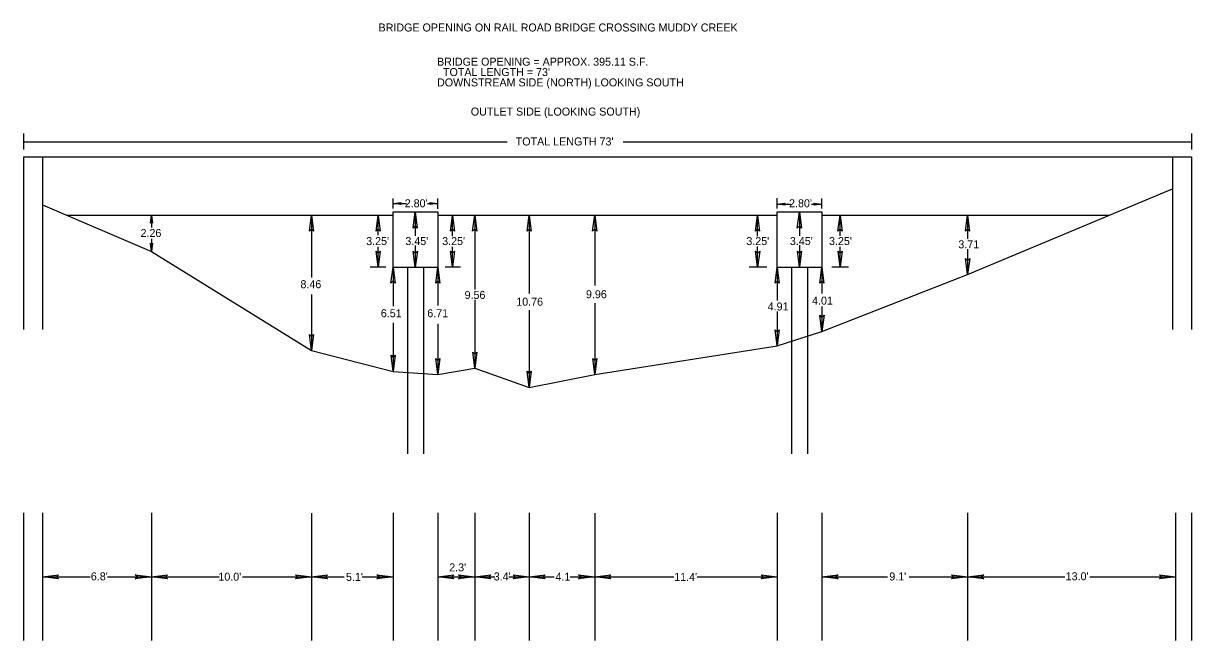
# Model space of a CAD drawing. Extents: x -200 to 949611, y -218 to 425120.
# Drawn here: x 948881 to 949611, y 424135 to 424521 of the extents above; entities that cross this region are included whole.
import ezdxf

# ---------------------------------------------------------------- set-up
doc = ezdxf.new("R2010")
doc.units = 0
doc.layers.add('SURVEY - PROFILE - Drainage - Bridge Hydraulic Data with Text', color=7, linetype='Continuous')

msp = doc.modelspace()

# ---------------------------------------------------------------- linework, layer by layer
at = {"layer": 'SURVEY - PROFILE - Drainage - Bridge Hydraulic Data with Text'}
for p, q in [((948880.64, 424451.86), (948880.64, 424441.85)), ((949610.64, 424451.86), (949610.64, 424441.85)), ((948880.64, 424446.65), (949182.88, 424446.65)), ((949255.53, 424446.65), (949610.64, 424446.65)), ((948880.64, 424437.28), (948892.64, 424437.28)), ((948880.64, 424437.28), (948880.64, 424329.47)), ((948892.64, 424437.28), (948892.64, 424329.47)), ((948892.64, 424437.28), (949598.64, 424437.28)), ((949598.64, 424437.28), (949598.64, 424329.47)), ((949598.64, 424437.28), (949610.64, 424437.28)), ((949610.64, 424437.28), (949610.64, 424329.47)), ((949470.64, 424363.78), (949598.64, 424417.28)), ((949111.64, 424405.01), (949111.64, 424411.31)), ((949111.64, 424408.14), (949120.13, 424408.14)), ((949133.21, 424408.14), (949139.64, 424408.14)), ((949139.64, 424404.94), (949139.64, 424411.31)), ((949351.64, 424405.04), (949351.64, 424411.41)), ((949351.64, 424407.7), (949359.96, 424407.7)), ((949373.01, 424407.7), (949379.64, 424407.7)), ((949379.64, 424405.01), (949379.64, 424411.38)), ((948892.64, 424407.28), (948960.64, 424378.28)), ((948907.64, 424400.88), (949111.64, 424400.88)), ((948960.64, 424400.88), (948960.64, 424393.08)), ((949060.64, 424400.88), (949060.64, 424361.9)), ((949102.32, 424388.33), (949102.32, 424400.88)), ((949111.64, 424402.88), (949139.64, 424402.88)), ((949111.64, 424368.38), (949111.64, 424402.88)), ((949125.56, 424402.88), (949125.56, 424388.01)), ((949139.64, 424402.88), (949139.64, 424368.38)), ((949139.64, 424400.88), (949351.64, 424400.88)), ((949148.81, 424387.85), (949148.81, 424400.88)), ((949162.64, 424400.88), (949162.64, 424354.38)), ((949196.64, 424400.88), (949196.64, 424352.04)), ((949237.64, 424400.88), (949237.64, 424356.86)), ((949339.47, 424387.86), (949339.47, 424400.88)), ((949351.64, 424402.88), (949379.64, 424402.88)), ((949351.64, 424368.38), (949351.64, 424402.88)), ((949365.52, 424402.88), (949365.52, 424387.99)), ((949379.64, 424402.88), (949379.64, 424368.38)), ((949379.64, 424400.88), (949559.4, 424400.88)), ((949390.93, 424387.93), (949390.93, 424400.88)), ((949470.64, 424400.88), (949470.64, 424386.1)), ((948960.64, 424386.07), (948960.64, 424378.28)), ((948960.64, 424378.28), (949060.64, 424316.28)), ((949102.32, 424368.38), (949102.32, 424381.19)), ((949125.56, 424381.99), (949125.56, 424368.38)), ((949148.81, 424368.38), (949148.81, 424381.19)), ((949339.47, 424368.38), (949339.47, 424381.28)), ((949365.52, 424382.05), (949365.52, 424368.38)), ((949390.93, 424368.38), (949390.93, 424381.08)), ((949470.64, 424379.59), (949470.64, 424363.78)), ((949107.12, 424368.38), (949097.44, 424368.38)), ((949111.64, 424368.38), (949139.64, 424368.38)), ((949111.64, 424368.38), (949111.64, 424344.08)), ((949120.64, 424368.38), (949120.64, 424251.68)), ((949130.64, 424368.38), (949130.64, 424251.68)), ((949139.64, 424368.38), (949139.64, 424344.36)), ((949153.68, 424368.38), (949144.13, 424368.38)), ((949345.12, 424368.38), (949334.1, 424368.38)), ((949351.64, 424368.38), (949379.64, 424368.38)), ((949351.64, 424368.38), (949351.64, 424347.48)), ((949360.64, 424368.38), (949360.64, 424251.68)), ((949370.64, 424368.38), (949370.64, 424251.68)), ((949379.64, 424368.38), (949379.64, 424351.9)), ((949379.64, 424328.28), (949470.64, 424363.78)), ((949396.21, 424368.38), (949385.8, 424368.38)), ((949060.64, 424351.3), (949060.64, 424316.28)), ((949162.64, 424347.98), (949162.64, 424305.28)), ((949237.64, 424345.96), (949237.64, 424301.28)), ((949379.64, 424343.87), (949379.64, 424328.28)), ((949196.64, 424341.58), (949196.64, 424293.28)), ((949351.64, 424340.71), (949351.64, 424319.28)), ((949111.64, 424333.63), (949111.64, 424303.28)), ((949139.64, 424333.01), (949139.64, 424301.28)), ((949351.64, 424319.28), (949379.64, 424328.28)), ((949060.64, 424316.28), (949111.64, 424303.28)), ((949237.64, 424301.28), (949351.64, 424319.28)), ((949139.64, 424301.28), (949162.64, 424305.28)), ((949162.64, 424305.28), (949196.64, 424293.28)), ((949111.64, 424303.28), (949139.64, 424301.28)), ((949196.64, 424293.28), (949237.64, 424301.28)), ((948880.64, 424214.92), (948880.64, 424135.07)), ((948892.64, 424214.92), (948892.64, 424135.07)), ((948960.64, 424214.82), (948960.64, 424135.07)), ((949060.64, 424214.76), (949060.64, 424135.07)), ((949111.64, 424214.92), (949111.64, 424135.07)), ((949139.64, 424214.92), (949139.64, 424135.07)), ((949162.64, 424214.97), (949162.64, 424174.91)), ((949196.64, 424214.97), (949196.64, 424135.07)), ((949237.64, 424214.76), (949237.64, 424135.07)), ((949351.64, 424214.92), (949351.64, 424135.07)), ((949379.64, 424214.92), (949379.64, 424135.07)), ((949470.64, 424214.82), (949470.64, 424135.07)), ((949600.64, 424214.92), (949600.64, 424135.07)), ((949610.64, 424214.92), (949610.64, 424135.07)), ((948892.64, 424174.92), (948922.31, 424174.92)), ((948933.22, 424174.92), (948960.62, 424174.92)), ((948960.62, 424174.92), (949002.94, 424174.92)), ((949017.61, 424174.92), (949060.67, 424174.92)), ((949060.67, 424174.92), (949081.08, 424174.92)), ((949092.34, 424174.92), (949111.64, 424174.92)), ((949139.64, 424174.92), (949175.16, 424174.92)), ((949162.64, 424174.91), (949162.64, 424135.07)), ((949183.92, 424174.92), (949196.67, 424174.92)), ((949196.67, 424174.92), (949212.38, 424174.92)), ((949222.31, 424174.92), (949237.77, 424174.92)), ((949237.77, 424174.92), (949287.12, 424174.92)), ((949301.65, 424174.92), (949351.64, 424174.92)), ((949379.64, 424174.92), (949420.57, 424174.92)), ((949434.13, 424174.92), (949470.68, 424174.92)), ((949470.68, 424174.92), (949531.46, 424174.92)), ((949547.08, 424174.92), (949600.64, 424174.92))]:
    msp.add_line(p, q, dxfattribs=at)
for points in [[(949111.64, 424408.14), (949116.69, 424408.79), (949116.04, 424408.14), (949116.69, 424407.49)], [(949139.64, 424408.14), (949134.59, 424407.49), (949135.24, 424408.14), (949134.59, 424408.79)], [(949351.64, 424407.7), (949356.69, 424408.35), (949356.04, 424407.7), (949356.69, 424407.05)], [(949379.64, 424407.7), (949374.59, 424407.05), (949375.24, 424407.7), (949374.59, 424408.35)], [(948960.64, 424400.88), (948961.29, 424395.83), (948960.64, 424396.48), (948959.99, 424395.83)], [(949060.64, 424400.88), (949061.89, 424390.83), (949060.64, 424392.13), (949059.34, 424390.83)], [(949102.32, 424400.88), (949103.57, 424390.83), (949102.32, 424392.13), (949101.02, 424390.83)], [(949125.56, 424402.88), (949126.81, 424392.83), (949125.56, 424394.13), (949124.26, 424392.83)], [(949148.81, 424400.88), (949150.06, 424390.83), (949148.81, 424392.13), (949147.51, 424390.83)], [(949162.64, 424400.88), (949163.89, 424390.83), (949162.64, 424392.13), (949161.34, 424390.83)], [(949196.64, 424400.88), (949197.89, 424390.83), (949196.64, 424392.13), (949195.34, 424390.83)], [(949237.64, 424400.88), (949238.89, 424390.83), (949237.64, 424392.13), (949236.34, 424390.83)], [(949339.47, 424400.88), (949340.72, 424390.83), (949339.47, 424392.13), (949338.17, 424390.83)], [(949365.52, 424402.88), (949366.77, 424392.83), (949365.52, 424394.13), (949364.22, 424392.83)], [(949390.93, 424400.88), (949392.18, 424390.83), (949390.93, 424392.13), (949389.63, 424390.83)], [(949470.64, 424400.88), (949471.89, 424390.83), (949470.64, 424392.13), (949469.34, 424390.83)], [(948960.64, 424378.28), (948959.99, 424383.33), (948960.64, 424382.68), (948961.29, 424383.33)], [(949102.32, 424368.38), (949101.07, 424378.43), (949102.32, 424377.13), (949103.62, 424378.43)], [(949125.56, 424368.38), (949124.31, 424378.43), (949125.56, 424377.13), (949126.86, 424378.43)], [(949148.81, 424368.38), (949147.56, 424378.43), (949148.81, 424377.13), (949150.11, 424378.43)], [(949339.47, 424368.38), (949338.22, 424378.43), (949339.47, 424377.13), (949340.77, 424378.43)], [(949365.52, 424368.38), (949364.27, 424378.43), (949365.52, 424377.13), (949366.82, 424378.43)], [(949390.93, 424368.38), (949389.68, 424378.43), (949390.93, 424377.13), (949392.23, 424378.43)], [(949470.64, 424363.78), (949469.39, 424373.83), (949470.64, 424372.53), (949471.94, 424373.83)], [(949111.64, 424368.38), (949112.89, 424358.33), (949111.64, 424359.63), (949110.34, 424358.33)], [(949139.64, 424368.38), (949140.89, 424358.33), (949139.64, 424359.63), (949138.34, 424358.33)], [(949351.64, 424368.38), (949352.89, 424358.33), (949351.64, 424359.63), (949350.34, 424358.33)], [(949379.64, 424368.38), (949380.89, 424358.33), (949379.64, 424359.63), (949378.34, 424358.33)], [(949379.64, 424328.28), (949378.39, 424338.33), (949379.64, 424337.03), (949380.94, 424338.33)], [(949351.64, 424319.28), (949350.39, 424329.33), (949351.64, 424328.03), (949352.94, 424329.33)], [(949060.64, 424316.28), (949059.39, 424326.33), (949060.64, 424325.03), (949061.94, 424326.33)], [(949111.64, 424303.28), (949110.39, 424313.33), (949111.64, 424312.03), (949112.94, 424313.33)], [(949162.64, 424305.28), (949161.39, 424315.33), (949162.64, 424314.03), (949163.94, 424315.33)], [(949139.64, 424301.28), (949138.39, 424311.33), (949139.64, 424310.03), (949140.94, 424311.33)], [(949237.64, 424301.28), (949236.39, 424311.33), (949237.64, 424310.03), (949238.94, 424311.33)], [(949196.64, 424293.28), (949195.39, 424303.33), (949196.64, 424302.03), (949197.94, 424303.33)], [(948892.64, 424174.92), (948902.69, 424176.17), (948901.39, 424174.92), (948902.69, 424173.62)], [(948960.64, 424174.92), (948950.59, 424173.67), (948951.89, 424174.92), (948950.59, 424176.22)], [(948960.64, 424174.92), (948970.69, 424176.17), (948969.39, 424174.92), (948970.69, 424173.62)], [(949060.64, 424174.92), (949050.59, 424173.67), (949051.89, 424174.92), (949050.59, 424176.22)], [(949060.64, 424174.92), (949070.69, 424176.17), (949069.39, 424174.92), (949070.69, 424173.62)], [(949111.64, 424174.92), (949101.59, 424173.67), (949102.89, 424174.92), (949101.59, 424176.22)], [(949139.64, 424174.92), (949149.69, 424176.17), (949148.39, 424174.92), (949149.69, 424173.62)], [(949162.64, 424174.92), (949152.59, 424173.67), (949153.89, 424174.92), (949152.59, 424176.22)], [(949162.64, 424174.92), (949172.69, 424176.17), (949171.39, 424174.92), (949172.69, 424173.62)], [(949196.64, 424174.92), (949186.59, 424173.67), (949187.89, 424174.92), (949186.59, 424176.22)], [(949196.64, 424174.92), (949206.69, 424176.17), (949205.39, 424174.92), (949206.69, 424173.62)], [(949237.64, 424174.92), (949227.59, 424173.67), (949228.89, 424174.92), (949227.59, 424176.22)], [(949237.64, 424174.92), (949247.69, 424176.17), (949246.39, 424174.92), (949247.69, 424173.62)], [(949351.64, 424174.92), (949341.59, 424173.67), (949342.89, 424174.92), (949341.59, 424176.22)], [(949379.64, 424174.92), (949389.69, 424176.17), (949388.39, 424174.92), (949389.69, 424173.62)], [(949470.64, 424174.92), (949460.59, 424173.67), (949461.89, 424174.92), (949460.59, 424176.22)], [(949470.64, 424174.92), (949480.69, 424176.17), (949479.39, 424174.92), (949480.69, 424173.62)], [(949600.64, 424174.92), (949590.59, 424173.67), (949591.89, 424174.92), (949590.59, 424176.22)]]:
    msp.add_lwpolyline(points, close=True, dxfattribs=at)
for points in [[(949111.64, 424408.14), (949116.69, 424408.79), (949116.04, 424408.14), (949116.69, 424407.49), (949111.64, 424408.14)], [(949139.64, 424408.14), (949134.59, 424407.49), (949135.24, 424408.14), (949134.59, 424408.79), (949139.64, 424408.14)], [(949351.64, 424407.7), (949356.69, 424408.35), (949356.04, 424407.7), (949356.69, 424407.05), (949351.64, 424407.7)], [(949379.64, 424407.7), (949374.59, 424407.05), (949375.24, 424407.7), (949374.59, 424408.35), (949379.64, 424407.7)], [(948960.64, 424400.88), (948961.29, 424395.83), (948960.64, 424396.48), (948959.99, 424395.83), (948960.64, 424400.88)], [(949060.64, 424400.88), (949061.89, 424390.83), (949060.64, 424392.13), (949059.34, 424390.83), (949060.64, 424400.88)], [(949102.32, 424400.88), (949103.57, 424390.83), (949102.32, 424392.13), (949101.02, 424390.83), (949102.32, 424400.88)], [(949125.56, 424402.88), (949126.81, 424392.83), (949125.56, 424394.13), (949124.26, 424392.83), (949125.56, 424402.88)], [(949148.81, 424400.88), (949150.06, 424390.83), (949148.81, 424392.13), (949147.51, 424390.83), (949148.81, 424400.88)], [(949162.64, 424400.88), (949163.89, 424390.83), (949162.64, 424392.13), (949161.34, 424390.83), (949162.64, 424400.88)], [(949196.64, 424400.88), (949197.89, 424390.83), (949196.64, 424392.13), (949195.34, 424390.83), (949196.64, 424400.88)], [(949237.64, 424400.88), (949238.89, 424390.83), (949237.64, 424392.13), (949236.34, 424390.83), (949237.64, 424400.88)], [(949339.47, 424400.88), (949340.72, 424390.83), (949339.47, 424392.13), (949338.17, 424390.83), (949339.47, 424400.88)], [(949365.52, 424402.88), (949366.77, 424392.83), (949365.52, 424394.13), (949364.22, 424392.83), (949365.52, 424402.88)], [(949390.93, 424400.88), (949392.18, 424390.83), (949390.93, 424392.13), (949389.63, 424390.83), (949390.93, 424400.88)], [(949470.64, 424400.88), (949471.89, 424390.83), (949470.64, 424392.13), (949469.34, 424390.83), (949470.64, 424400.88)], [(948960.64, 424378.28), (948959.99, 424383.33), (948960.64, 424382.68), (948961.29, 424383.33), (948960.64, 424378.28)], [(949102.32, 424368.38), (949101.07, 424378.43), (949102.32, 424377.13), (949103.62, 424378.43), (949102.32, 424368.38)], [(949125.56, 424368.38), (949124.31, 424378.43), (949125.56, 424377.13), (949126.86, 424378.43), (949125.56, 424368.38)], [(949148.81, 424368.38), (949147.56, 424378.43), (949148.81, 424377.13), (949150.11, 424378.43), (949148.81, 424368.38)], [(949339.47, 424368.38), (949338.22, 424378.43), (949339.47, 424377.13), (949340.77, 424378.43), (949339.47, 424368.38)], [(949365.52, 424368.38), (949364.27, 424378.43), (949365.52, 424377.13), (949366.82, 424378.43), (949365.52, 424368.38)], [(949390.93, 424368.38), (949389.68, 424378.43), (949390.93, 424377.13), (949392.23, 424378.43), (949390.93, 424368.38)], [(949470.64, 424363.78), (949469.39, 424373.83), (949470.64, 424372.53), (949471.94, 424373.83), (949470.64, 424363.78)], [(949111.64, 424368.38), (949112.89, 424358.33), (949111.64, 424359.63), (949110.34, 424358.33), (949111.64, 424368.38)], [(949139.64, 424368.38), (949140.89, 424358.33), (949139.64, 424359.63), (949138.34, 424358.33), (949139.64, 424368.38)], [(949351.64, 424368.38), (949352.89, 424358.33), (949351.64, 424359.63), (949350.34, 424358.33), (949351.64, 424368.38)], [(949379.64, 424368.38), (949380.89, 424358.33), (949379.64, 424359.63), (949378.34, 424358.33), (949379.64, 424368.38)], [(949379.64, 424328.28), (949378.39, 424338.33), (949379.64, 424337.03), (949380.94, 424338.33), (949379.64, 424328.28)], [(949351.64, 424319.28), (949350.39, 424329.33), (949351.64, 424328.03), (949352.94, 424329.33), (949351.64, 424319.28)], [(949060.64, 424316.28), (949059.39, 424326.33), (949060.64, 424325.03), (949061.94, 424326.33), (949060.64, 424316.28)], [(949111.64, 424303.28), (949110.39, 424313.33), (949111.64, 424312.03), (949112.94, 424313.33), (949111.64, 424303.28)], [(949162.64, 424305.28), (949161.39, 424315.33), (949162.64, 424314.03), (949163.94, 424315.33), (949162.64, 424305.28)], [(949139.64, 424301.28), (949138.39, 424311.33), (949139.64, 424310.03), (949140.94, 424311.33), (949139.64, 424301.28)], [(949237.64, 424301.28), (949236.39, 424311.33), (949237.64, 424310.03), (949238.94, 424311.33), (949237.64, 424301.28)], [(949196.64, 424293.28), (949195.39, 424303.33), (949196.64, 424302.03), (949197.94, 424303.33), (949196.64, 424293.28)], [(948892.64, 424174.92), (948902.69, 424176.17), (948901.39, 424174.92), (948902.69, 424173.62), (948892.64, 424174.92)], [(948960.64, 424174.92), (948950.59, 424173.67), (948951.89, 424174.92), (948950.59, 424176.22), (948960.64, 424174.92)], [(948960.64, 424174.92), (948970.69, 424176.17), (948969.39, 424174.92), (948970.69, 424173.62), (948960.64, 424174.92)], [(949060.64, 424174.92), (949050.59, 424173.67), (949051.89, 424174.92), (949050.59, 424176.22), (949060.64, 424174.92)], [(949060.64, 424174.92), (949070.69, 424176.17), (949069.39, 424174.92), (949070.69, 424173.62), (949060.64, 424174.92)], [(949111.64, 424174.92), (949101.59, 424173.67), (949102.89, 424174.92), (949101.59, 424176.22), (949111.64, 424174.92)], [(949139.64, 424174.92), (949149.69, 424176.17), (949148.39, 424174.92), (949149.69, 424173.62), (949139.64, 424174.92)], [(949162.64, 424174.92), (949152.59, 424173.67), (949153.89, 424174.92), (949152.59, 424176.22), (949162.64, 424174.92)], [(949162.64, 424174.92), (949172.69, 424176.17), (949171.39, 424174.92), (949172.69, 424173.62), (949162.64, 424174.92)], [(949196.64, 424174.92), (949186.59, 424173.67), (949187.89, 424174.92), (949186.59, 424176.22), (949196.64, 424174.92)], [(949196.64, 424174.92), (949206.69, 424176.17), (949205.39, 424174.92), (949206.69, 424173.62), (949196.64, 424174.92)], [(949237.64, 424174.92), (949227.59, 424173.67), (949228.89, 424174.92), (949227.59, 424176.22), (949237.64, 424174.92)], [(949237.64, 424174.92), (949247.69, 424176.17), (949246.39, 424174.92), (949247.69, 424173.62), (949237.64, 424174.92)], [(949351.64, 424174.92), (949341.59, 424173.67), (949342.89, 424174.92), (949341.59, 424176.22), (949351.64, 424174.92)], [(949379.64, 424174.92), (949389.69, 424176.17), (949388.39, 424174.92), (949389.69, 424173.62), (949379.64, 424174.92)], [(949470.64, 424174.92), (949460.59, 424173.67), (949461.89, 424174.92), (949460.59, 424176.22), (949470.64, 424174.92)], [(949470.64, 424174.92), (949480.69, 424176.17), (949479.39, 424174.92), (949480.69, 424173.62), (949470.64, 424174.92)], [(949600.64, 424174.92), (949590.59, 424173.67), (949591.89, 424174.92), (949590.59, 424176.22), (949600.64, 424174.92)]]:
    msp.add_lwpolyline(points, dxfattribs=at)

# ---------------------------------------------------------------- texts
for s, p in [('BRIDGE OPENING ON RAIL ROAD BRIDGE CROSSING MUDDY CREEK', (949102.57, 424515.64)), ('BRIDGE OPENING = APPROX. 395.11 S.F.', (949139.14, 424494.27)), ("  TOTAL LENGTH = 73' ", (949139.14, 424487.8)), ('DOWNSTREAM SIDE (NORTH) LOOKING SOUTH', (949139.14, 424481.33)), ('OUTLET SIDE (LOOKING SOUTH)', (949160.23, 424463.1)), ("TOTAL LENGTH 73'", (949188.28, 424444.43)), ("2.80'", (949118.94, 424405.81)), ("2.80'", (949359.11, 424405.81)), ('2.26', (948953.86, 424387.23)), ("3.25'", (949094.86, 424382.21)), ("3.45'", (949119.35, 424382.21)), ("3.25'", (949142.35, 424382.21)), ("3.25'", (949332.4, 424382.21)), ("3.45'", (949359.61, 424382.21)), ("3.25'", (949384.06, 424382.21)), ('3.71', (949464.86, 424380.16)), ('8.46', (949053.79, 424355.25)), ('9.56', (949156.34, 424348.56)), ('10.76', (949188.63, 424344.32)), ('9.96', (949232.18, 424348.99)), ('4.01', (949373.46, 424345)), ('6.51', (949104, 424337.11)), ('6.71', (949133.03, 424337.11)), ('4.91', (949345.72, 424341.33)), ("2.3'", (949146.73, 424178.34)), ("6.8'", (948922.79, 424172.73)), ("10.0'", (949002.5, 424172.52)), ("5.1'", (949082.22, 424172.4)), ("3.4'", (949174.54, 424172.66)), ('4.1', (949213.12, 424172.52)), ("11.4'", (949287.33, 424172.36)), ("9.1'", (949421.71, 424172.66)), ("13.0'", (949531.93, 424172.78))]:
    msp.add_text(s, height=5, dxfattribs=at).set_placement(p)

doc.saveas('drawing.dxf')
